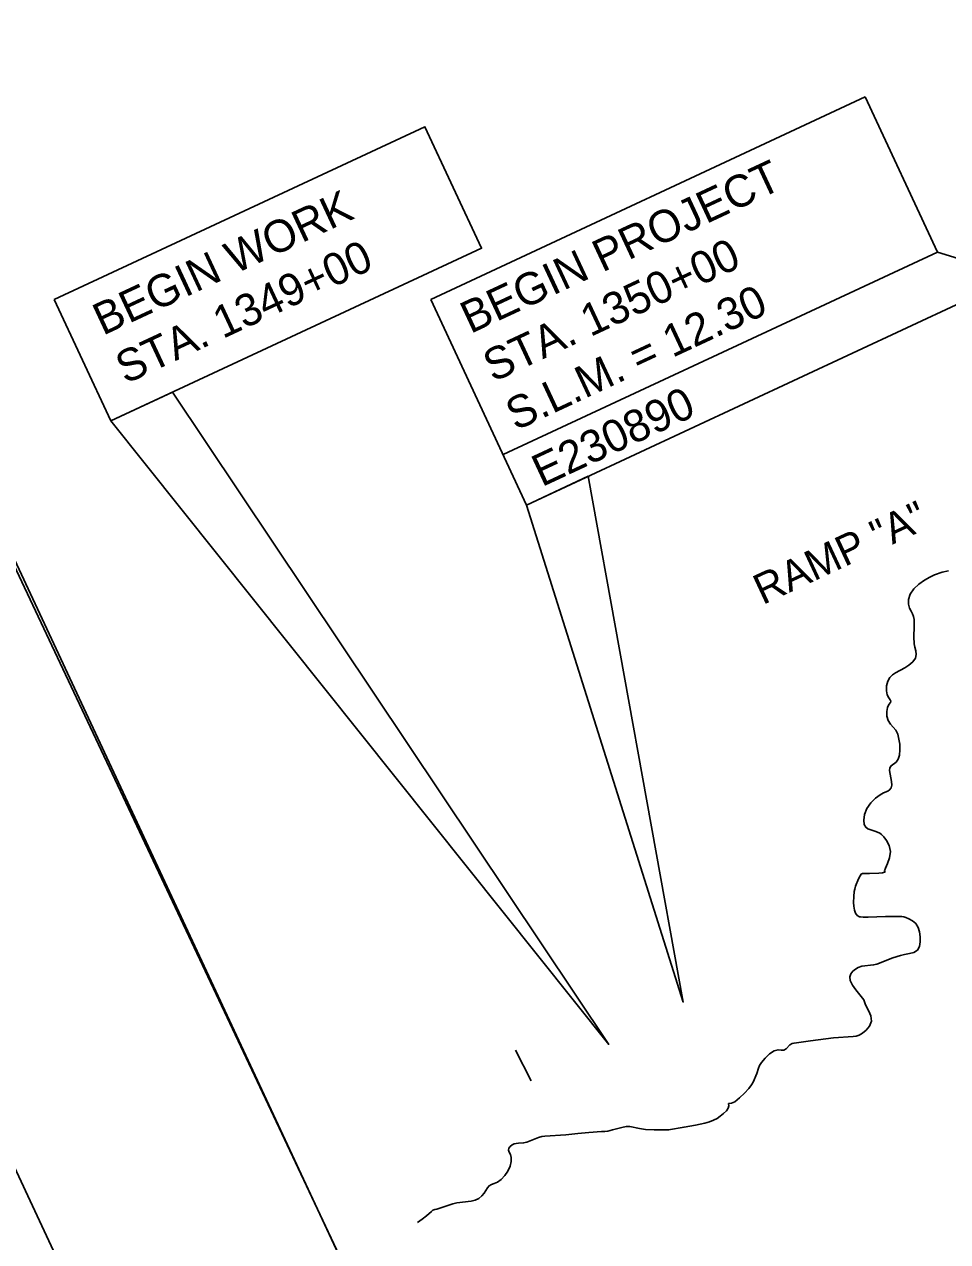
# Model space of a CAD drawing. Extents: x -310467766 to 17062430, y -322263100 to 8322522.
# Drawn here: x 1392973 to 1394051, y 571443 to 572866 of the extents above; entities that cross this region are included whole.
import ezdxf

# ---------------------------------------------------------------- set-up
doc = ezdxf.new("R2010")
doc.units = 0
for name, color, linetype in [('DT_X_Contour_Minor', 7, 'Continuous'), ('DT_X_Contour_Text', 7, 'Continuous'), ('Level 40', 7, 'Continuous'), ('SC_Scratch1', 7, 'Continuous'), ('SH_Border', 7, 'Continuous')]:
    doc.layers.add(name, color=color, linetype=linetype)

msp = doc.modelspace()

# ---------------------------------------------------------------- linework, layer by layer
at = {"layer": 'DT_X_Contour_Minor'}
for points in [[(1393949.6, 571822.8), (1393948.4, 571823), (1393945.6, 571824.5), (1393943.7, 571827.1), (1393942.4, 571830.8), (1393941.7, 571835.3), (1393941.4, 571839.7), (1393941.6, 571846.8), (1393942.3, 571852.3), (1393942.9, 571855.2), (1393943.9, 571858.7), (1393947.4, 571867.3), (1393949, 571870.8), (1393950.3, 571872.8), (1393952, 571873.5), (1393960.2, 571873.6), (1393971.1, 571873.7), (1393975.3, 571874.2), (1393978, 571875.1), (1393977.8, 571875.4), (1393977.7, 571876.7), (1393978.6, 571879.7), (1393981, 571885), (1393983.5, 571891.9), (1393984.6, 571899.2), (1393983.2, 571906.1), (1393980.1, 571912.1), (1393976.7, 571916.5), (1393974.2, 571919.1), (1393972.2, 571920.6), (1393967.4, 571922.5), (1393958.2, 571925.8), (1393955.6, 571927.5), (1393953.9, 571930.6), (1393953.3, 571935.8), (1393954.1, 571942.3), (1393956.9, 571949.3), (1393961.6, 571955.9), (1393967.2, 571961.4), (1393972.5, 571965.5), (1393976.4, 571967.7), (1393981.4, 571969.7), (1393983.5, 571971.2), (1393985.2, 571973.4), (1393986, 571976.7), (1393985.9, 571981), (1393983.6, 571994), (1393984, 571997), (1393985.4, 571999.3), (1393991.1, 572003.6), (1393993.7, 572007), (1393995.2, 572011.9), (1393995.6, 572018), (1393995.3, 572024.5), (1393994.5, 572030.6), (1393993.2, 572036.2), (1393991, 572040.9), (1393987.9, 572044.6), (1393984.7, 572048.1), (1393982, 572052.1), (1393980.5, 572057.3), (1393980.3, 572062.8), (1393981.2, 572067.6), (1393982.8, 572071), (1393984.4, 572073.3), (1393985, 572074.9), (1393984.2, 572076.5), (1393982.5, 572078.7), (1393980.7, 572082.1), (1393979.8, 572087), (1393980, 572092.6), (1393981.3, 572098.1), (1393983.8, 572102.4), (1393987, 572105.7), (1393990.5, 572108.1), (1394001.5, 572113.9), (1394006.2, 572117), (1394010.7, 572120.9), (1394013.8, 572125.1), (1394014.7, 572129.4), (1394014, 572133.7), (1394012.9, 572137.9), (1394012.2, 572142), (1394011.9, 572150), (1394012.1, 572162.1), (1394012.2, 572170.3), (1394011.6, 572173.9), (1394010.4, 572176.8), (1394008.6, 572179.8), (1394006.9, 572183.4), (1394005.7, 572188.1), (1394005.6, 572193.8), (1394007.5, 572199.9), (1394011.8, 572205.9), (1394017.8, 572211.5), (1394024.3, 572216.2), (1394030.5, 572219.8), (1394036.1, 572222.4), (1394044.8, 572225.4), (1394052.4, 572227.3)], [(1393949.7, 571822.9), (1393952.7, 571822.4), (1393958.4, 571822.4), (1393978.6, 571823.3), (1393997.9, 571823.2), (1394000, 571822.9), (1394002.5, 571822.1), (1394006.1, 571820.6), (1394010.4, 571818.2), (1394014.3, 571814.9), (1394016.9, 571810.5), (1394018.5, 571805.3), (1394019.2, 571799.6), (1394019.3, 571793.6), (1394018.4, 571788.1), (1394016, 571783.9), (1394011.8, 571781.3), (1394006.6, 571779.9), (1394001.1, 571778.9), (1393996.2, 571777.8), (1393987.5, 571774.9), (1393968.6, 571767.4), (1393964.8, 571766.6), (1393951, 571765.2), (1393947, 571763.8), (1393943.6, 571761.8), (1393940.7, 571759.3), (1393938.3, 571756.4), (1393936.9, 571752.8), (1393937.4, 571748.4), (1393940.1, 571743), (1393944, 571737.6), (1393953.6, 571725.8), (1393955.1, 571721.1), (1393956.7, 571717.8), (1393959.3, 571712.8), (1393961.8, 571707), (1393962.4, 571700.9), (1393960.2, 571695.3), (1393956.1, 571690.5), (1393951.7, 571686.9), (1393947.9, 571684.7), (1393944.5, 571683.5), (1393940.8, 571683), (1393918.2, 571681.5), (1393891.1, 571678), (1393871.9, 571675.4), (1393869.6, 571674.7), (1393867.2, 571673.3), (1393862.7, 571668.5), (1393860.1, 571667), (1393857, 571667.1), (1393853.2, 571667.5), (1393848.7, 571666.4), (1393843.4, 571662.8), (1393838.2, 571657.6), (1393834, 571652.6), (1393831.6, 571649), (1393830.4, 571646.2), (1393828.3, 571640), (1393824.1, 571629.7), (1393822.2, 571626.5), (1393819, 571622.4), (1393814, 571616.9), (1393808.1, 571611.2), (1393802.6, 571606.9), (1393798.7, 571605), (1393795.4, 571604.7), (1393795.6, 571601.9), (1393795, 571599.3), (1393792.9, 571596.3), (1393789.6, 571593.1), (1393785.8, 571590.1), (1393782, 571587.4), (1393778, 571585.1), (1393773.2, 571583.2), (1393767.6, 571581.6), (1393756.8, 571579.5), (1393743.5, 571577.3), (1393725.4, 571573.9), (1393723.1, 571573.8), (1393708.6, 571573.9), (1393698.4, 571574.3), (1393691.5, 571575.4), (1393680.2, 571577.7), (1393677.7, 571577.9), (1393675.7, 571577.8), (1393670.6, 571576.7), (1393659.9, 571573.9), (1393654.3, 571572.4), (1393651.1, 571572), (1393647.1, 571572), (1393632.4, 571570.9), (1393619.3, 571569.6), (1393605.2, 571568), (1393580.8, 571566.6), (1393577.4, 571566.1), (1393573.6, 571565), (1393559.8, 571559.7), (1393556, 571558.8), (1393550.1, 571558.3)], [(1393550.1, 571558.3), (1393547.5, 571558), (1393545, 571557.5), (1393542.6, 571556.4), (1393540.4, 571554.7), (1393538.8, 571552.5), (1393538.3, 571550.2), (1393539.1, 571547.9), (1393540.6, 571545.2), (1393541.7, 571541.6), (1393541.7, 571536.9), (1393540.4, 571531.4), (1393537.8, 571525.7), (1393534.2, 571520.5), (1393530, 571516.1), (1393525.7, 571513), (1393521.8, 571511.2), (1393518.5, 571510), (1393515.8, 571508.7), (1393513.9, 571506.4), (1393510.1, 571500.1), (1393507.2, 571496.8), (1393503.6, 571493.9), (1393499.4, 571491.8), (1393494.8, 571490.6), (1393477.9, 571488.7), (1393473.5, 571487.5), (1393454.7, 571481.4), (1393452.2, 571480.8), (1393450.2, 571480), (1393448.3, 571478.7), (1393442.6, 571473.5), (1393437.7, 571469.6), (1393432.2, 571465.6)]]:
    msp.add_lwpolyline(points, dxfattribs=at)
at = {"layer": 'DT_X_Contour_Text'}
msp.add_line((1393564.9, 571631.4), (1393546.5, 571667), dxfattribs=at)
at = {"layer": 'Level 40'}
for p, q in [((1393447.5, 572544.1), (1393955, 572780.8)), ((1394039.5, 572599.6), (1393955, 572780.8)), ((1393532, 572362.9), (1394039.5, 572599.6)), ((1393532, 572362.9), (1394039.5, 572599.6)), ((1394039.5, 572599.6), (1394084.7, 572585.5)), ((1393447.5, 572544.1), (1393559.4, 572304)), ((1393559.4, 572304), (1394067, 572540.6))]:
    msp.add_line(p, q, dxfattribs=at)
for points in [[(1393007.8, 572544), (1393440.7, 572745.9), (1393506.9, 572604.1), (1393073.9, 572402.2)], [(1393073.9, 572402.2), (1393655.5, 571673.7), (1393146, 572435.8)], [(1393559.4, 572304), (1393742.5, 571723.3), (1393631.5, 572337.6)]]:
    msp.add_lwpolyline(points, close=True, dxfattribs=at)
at = {"layer": 'SC_Scratch1'}
msp.add_lwpolyline([(1392212.4, 573822.1), (1393676.3, 570715.4), (1396857.5, 571041.4), (1399761.2, 572912.7), (1399601.4, 573251.9), (1400998.4, 575913.7), (1400551.7, 577289.3)], close=True, dxfattribs=at)
at = {"layer": 'SH_Border'}
for points in [[(1391939.2, 574432), (1400639.7, 578489.1), (1403302.2, 572779.4), (1394601.7, 568722.3)], [(1391667.3, 574305.2), (1391939.2, 574432), (1394601.7, 568722.3), (1394329.8, 568595.5)]]:
    msp.add_lwpolyline(points, close=True, dxfattribs=at)

# ---------------------------------------------------------------- texts
at = {"layer": 'Level 40'}
for s, height, p in [('BEGIN PROJECT', 37.5, (1393493.9, 572503.7)), ('BEGIN WORK', 37.5, (1393064.6, 572501.6)), ('STA. 1349+00', 37.5, (1393091, 572444.9)), ('STA. 1350+00', 37.5, (1393520.3, 572447.1)), ('S.L.M. = 12.30', 37.5, (1393546.7, 572390.4)), ('E230890', 37.5, (1393577.3, 572324.7)), ('RAMP "A"', 35.5, (1393835.3, 572186.9))]:
    msp.add_text(s, height=height, rotation=25, dxfattribs=at).set_placement(p)

doc.saveas('drawing.dxf')
